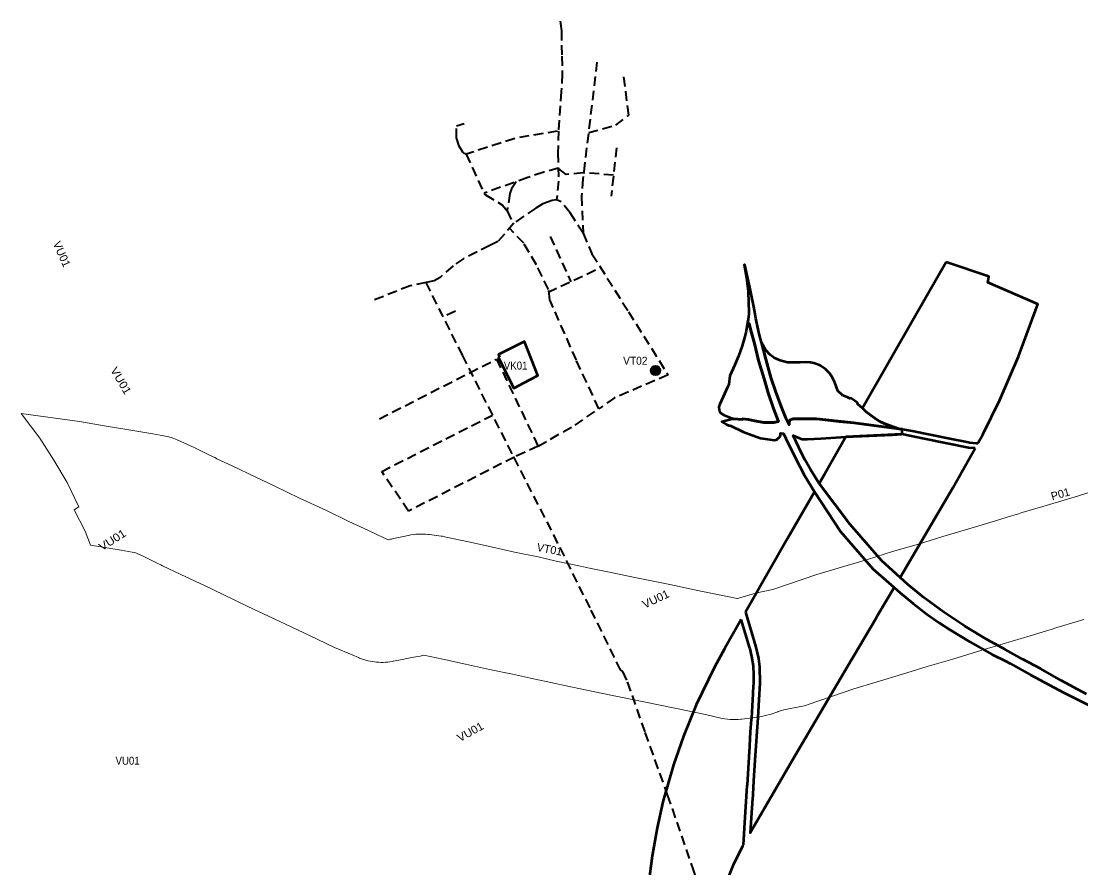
# Model space of a CAD drawing. Extents: x -650145 to -642675, y -1074338 to -1066724.
# Drawn here: x -649600 to -646953, y -1068839 to -1066724 of the extents above; entities that cross this region are included whole.
import ezdxf

# ---------------------------------------------------------------- set-up
doc = ezdxf.new("R2010")
doc.units = 0
doc.header["$LTSCALE"] = 8
doc.linetypes.add('MEDIUM_DASHED', pattern=[4.5, 3, -1.5])
for name, color, linetype in [('1', 7, 'Continuous'), ('17', 7, 'Continuous'), ('2', 7, 'Continuous')]:
    doc.layers.add(name, color=color, linetype=linetype)
for name, color, linetype, lineweight in [('12', 7, 'MEDIUM_DASHED', 40), ('15', 7, 'Continuous', 13), ('44', 7, 'Continuous', 53), ('45', 7, 'Continuous', 53)]:
    doc.layers.add(name, color=color, linetype=linetype, lineweight=lineweight)

msp = doc.modelspace()

# ---------------------------------------------------------------- hatches: boundary and pattern name
at = {"layer": '15'}
msp.add_hatch(color=256, dxfattribs=at).paths.add_polyline_path([(-648003.776, -1067596.576, 1), (-648027.301, -1067596.576, 1)])

# ---------------------------------------------------------------- linework, layer by layer
at = {"layer": '12'}
for p, q in [((-648112.923, -1067040.185), (-648126.71, -1067161.68)), ((-648278.693, -1067262.163), (-648226.9, -1067375.166)), ((-648165.273, -1067346.538), (-648282.098, -1067400.808)), ((-648515.199, -1067448.468), (-648546.557, -1067463.228))]:
    msp.add_line(p, q, dxfattribs=at)
for points in [[(-648254.111, -1066724.115), (-648250.825, -1066748.213), (-648249.73, -1066811.744), (-648248.971, -1066855.783), (-648251.033, -1066899.78), (-648258.055, -1066998.612), (-648259.37, -1067053.379), (-648258.055, -1067123.482), (-648262.874, -1067170.801), (-648274.266, -1067172.334), (-648297.049, -1067180.221), (-648315.013, -1067191.174), (-648369.562, -1067228.854), (-648409.651, -1067274.641), (-648429.367, -1067284.499), (-648494.475, -1067317.053), (-648521.596, -1067335.324), (-648554.018, -1067364.678), (-648568.696, -1067372.565), (-648588.85, -1067377.165), (-648628.502, -1067385.052), (-648726.865, -1067424.267)], [(-648161.945, -1066826.336), (-648197.181, -1067117.94), (-648200.826, -1067161.68), (-648196.766, -1067253.967), (-648228.816, -1067203.221), (-648251.518, -1067175.177), (-648262.874, -1067170.801)], [(-648182.601, -1067002.513), (-648115.19, -1066984.032), (-648082.101, -1066958.613), (-648096.04, -1066857.23)], [(-648488.5, -1067056.457), (-648493.497, -1067055.091), (-648496.863, -1067051.153), (-648505.895, -1067036.526), (-648512.776, -1067015.949), (-648512.582, -1066985.375), (-648494.033, -1066979.937)], [(-648261.097, -1066998.621), (-648367.277, -1067016.878), (-648488.5, -1067056.457), (-648443.711, -1067154.017)], [(-648258.664, -1067091.005), (-648295.035, -1067101.44), (-648334.906, -1067114.73), (-648443.711, -1067154.017), (-648440.351, -1067157.668), (-648398.143, -1067183.811), (-648386.313, -1067197.539), (-648370.813, -1067230.283)], [(-648120.689, -1067108.619), (-648196.172, -1067102.839), (-648238.811, -1067107.157), (-648258.654, -1067091.57)], [(-648364.124, -1067125.28), (-648375.197, -1067142.997), (-648379.372, -1067154.48), (-648386.313, -1067197.539)], [(-648196.766, -1067253.967), (-648174.431, -1067304.992), (-648083.383, -1067449.946), (-647984.432, -1067607.856), (-648117.975, -1067665.279), (-648157.356, -1067692.42), (-648213.545, -1067571.236), (-648279.612, -1067420.693), (-648282.899, -1067394.398), (-648313.139, -1067332.931), (-648344.694, -1067279.025), (-648380.675, -1067241.546)], [(-648589.741, -1067377.342), (-648498.624, -1067558.559), (-648369.855, -1067814.661), (-648270.948, -1068007.281), (-648177.599, -1068195.293), (-648103.97, -1068344.741), (-648098.419, -1068348.539), (-648086.184, -1068375.018), (-648042.175, -1068501.421), (-647986.295, -1068657.442), (-647921.652, -1068844.799), (-647896.268, -1068918.371), (-647865.117, -1068998.629), (-647819.537, -1069124.409), (-647801.818, -1069175.256), (-647812.644, -1069324.711), (-647825.015, -1069541.552), (-647823.978, -1069584.663), (-647594.109, -1069559.949), (-647342.265, -1069543.531), (-647205.182, -1069541.582), (-647108.806, -1069541.669), (-647047.983, -1069544.191), (-646818.857, -1069568.917)], [(-648705.527, -1067717.518), (-648412.884, -1067568.459), (-648309.025, -1067786), (-648368.053, -1067813.183), (-648633.004, -1067948.289), (-648699.635, -1067849.093), (-648423.205, -1067708.555)], [(-648309.025, -1067786), (-648216.797, -1067733.386), (-648157.356, -1067692.42)]]:
    msp.add_lwpolyline(points, dxfattribs=at)
at = {"layer": '15'}
for points in [[(-649382.683, -1067736.41), (-649454.621, -1067724.642), (-649600.146, -1067704.069)], [(-649600.146, -1067704.069), (-649553.44, -1067766.28), (-649518.25, -1067820.92), (-649485.13, -1067877.09), (-649456.24, -1067937.25), (-649467.89, -1067945.1), (-649440.52, -1067998.08), (-649427.146, -1068033.129), (-649350.073, -1068045.91)], [(-646911.586, -1067895.218), (-646969.855, -1067913.144), (-647032.093, -1067931.929), (-647048.173, -1067936.726), (-647099.576, -1067952.077), (-647114.132, -1067956.487), (-647120.451, -1067958.402), (-647126.241, -1067960.149), (-647166.751, -1067972.422), (-647233.528, -1067992.581), (-647298.314, -1068011.911), (-647358.997, -1068030.632), (-647423.612, -1068049.375), (-647486.376, -1068068.781), (-647550.936, -1068088.002), (-647612.779, -1068106.747), (-647722.769, -1068144.312), (-647762.416, -1068152.578), (-647765.408, -1068153.202), (-647771.336, -1068154.692), (-647774.267, -1068155.557), (-647802.757, -1068163.967), (-647805.815, -1068164.87), (-647810.703, -1068166.542), (-647812.571, -1068166.788), (-647827.9, -1068163.347), (-647906.909, -1068147.095), (-647980.144, -1068131.782), (-648067.22, -1068114.186), (-648126.418, -1068101.998), (-648181.06, -1068090.497), (-648203.256, -1068085.824), (-648264.087, -1068072.869), (-648309.141, -1068062.702), (-648367.602, -1068050.464), (-648426.568, -1068037.47), (-648482.748, -1068025.289), (-648538.58, -1068012.914), (-648541.779, -1068012.205), (-648548.234, -1068011.067), (-648551.482, -1068010.64), (-648580.682, -1068006.8), (-648583.733, -1068006.399), (-648589.862, -1068005.847), (-648596.008, -1068005.548), (-648602.162, -1068005.5), (-648608.312, -1068005.705), (-648614.449, -1068006.163), (-648620.561, -1068006.871), (-648626.64, -1068007.83), (-648629.657, -1068008.433), (-648649.671, -1068012.436), (-648670.491, -1068016.914), (-648675.031, -1068017.89), (-648677.625, -1068018.618), (-648680.26, -1068018.992), (-648683.7, -1068019.718), (-648693.991, -1068015.264), (-648732.758, -1067996.958), (-648781.439, -1067974.125), (-648839.635, -1067946.226), (-648905.118, -1067915.461), (-648966.216, -1067885.853), (-649013.828, -1067863.231), (-649073.136, -1067835.331), (-649111.1, -1067817.381), (-649111.919, -1067816.904), (-649116.61, -1067814.593), (-649129.493, -1067808.246), (-649168.436, -1067789.027), (-649210.538, -1067770.325), (-649214.568, -1067768.535), (-649222.823, -1067765.435), (-649231.246, -1067762.826), (-649239.808, -1067760.715), (-649244.144, -1067759.913), (-649270.928, -1067754.958), (-649346.551, -1067742.368), (-649382.683, -1067736.41)], [(-649350.073, -1068045.91), (-649322.852, -1068050.442), (-649316.134, -1068051.685), (-649295.764, -1068060.733), (-649262.167, -1068077.314), (-649255.583, -1068080.557), (-649251.7, -1068082.747), (-649246.836, -1068085.047), (-649201.104, -1068106.669), (-649142.052, -1068134.449), (-649096.004, -1068156.327), (-649034.322, -1068186.219), (-648968.265, -1068217.254), (-648909.981, -1068245.195), (-648860.502, -1068268.402), (-648817.649, -1068288.636), (-648773.793, -1068307.617), (-648757.876, -1068314.337), (-648755.322, -1068315.416), (-648750.136, -1068317.382), (-648744.882, -1068319.156), (-648739.566, -1068320.735), (-648734.195, -1068322.115), (-648728.777, -1068323.297), (-648723.319, -1068324.277), (-648717.828, -1068325.055), (-648712.312, -1068325.63), (-648706.779, -1068326), (-648701.236, -1068326.166), (-648695.69, -1068326.126), (-648690.15, -1068325.882), (-648684.623, -1068325.433), (-648679.116, -1068324.78), (-648673.637, -1068323.924), (-648670.915, -1068323.395), (-648657.024, -1068320.696), (-648628.18, -1068314.608), (-648619.413, -1068313.366), (-648614.155, -1068312.621), (-648603.771, -1068310.391), (-648594.694, -1068307.758), (-648546.992, -1068318.331), (-648490.632, -1068330.55)], [(-648127.18, -1068408.134), (-648040.556, -1068425.638), (-647967.831, -1068440.845), (-647890.98, -1068456.653), (-647852.243, -1068465.348), (-647849.022, -1068466.071), (-647842.522, -1068467.232), (-647835.978, -1068468.107), (-647829.402, -1068468.692), (-647822.806, -1068468.988), (-647816.203, -1068468.993), (-647809.607, -1068468.707), (-647803.03, -1068468.132), (-647799.757, -1068467.7), (-647755.597, -1068461.87), (-647751.962, -1068461.39), (-647744.747, -1068460.076), (-647737.604, -1068458.41), (-647730.552, -1068456.398), (-647727.079, -1068455.221), (-647712.829, -1068450.391), (-647710.163, -1068449.487), (-647709.521, -1068449.242), (-647695.198, -1068445.014), (-647652.454, -1068436.102), (-647647.917, -1068435.156), (-647638.976, -1068432.708), (-647634.59, -1068431.21), (-647520.761, -1068392.333), (-647464.624, -1068375.318), (-647399.264, -1068355.859), (-647337.508, -1068336.765), (-647272.983, -1068318.048), (-647211.206, -1068298.989), (-647147.292, -1068279.919), (-647079.909, -1068259.578), (-647039.419, -1068247.311), (-647033.609, -1068245.558), (-647027.128, -1068243.593), (-647013.164, -1068239.363), (-646962.367, -1068224.194), (-646945.867, -1068219.271)], [(-648490.632, -1068330.55), (-648430.618, -1068343.776), (-648372.899, -1068355.858), (-648328.353, -1068365.911), (-648265.404, -1068379.316), (-648242.86, -1068384.063), (-648187.562, -1068395.702), (-648127.18, -1068408.134)]]:
    msp.add_lwpolyline(points, dxfattribs=at)
at = {"layer": '15', "lineweight": 35}
msp.add_circle((-648015.538, -1067596.576), 11.762, dxfattribs=at)
at = {"layer": '44'}
for points in [[(-647400.63, -1067756.19), (-647540.208, -1067762.876), (-647593.267, -1067855.425), (-647606.818, -1067879.061)], [(-647217.611, -1067791.149), (-647233.83, -1067789.69), (-647345.11, -1067767.28), (-647400.63, -1067756.19)], [(-647405.026, -1068113.904), (-647273.297, -1067889.981), (-647217.611, -1067791.149)], [(-647606.818, -1067879.061), (-647530.038, -1067980.839), (-647451.024, -1068071.886), (-647405.026, -1068113.904)], [(-647464.94, -1068215.752), (-647461.188, -1068209.373), (-647419.713, -1068138.871), (-647472.338, -1068093.096), (-647553.628, -1067999.427), (-647618.773, -1067899.914), (-647685.819, -1068016.861)], [(-647685.819, -1068016.861), (-647781.346, -1068183.485), (-647791.055, -1068200.507)], [(-647791.055, -1068200.507), (-647765.22, -1068287.94), (-647759.412, -1068313.436)], [(-647801.797, -1068219.34), (-647843.6, -1068292.629), (-647868.214, -1068337.803), (-647914.339, -1068432.512), (-647946.187, -1068510.254), (-647971.074, -1068581.98), (-647997.27, -1068674.747), (-648011.775, -1068739.718), (-648023.914, -1068809.332), (-648030.73, -1068861.213), (-648038.596, -1068968.281)], [(-647771.413, -1068334.626), (-647774.94, -1068311.47), (-647779.55, -1068292.23), (-647780.07, -1068290.53), (-647801.797, -1068219.34)], [(-647768.02, -1068570.36), (-647770.94, -1068622.47), (-647772.85, -1068656.41), (-647773.08, -1068660.57), (-647773.4, -1068665.71), (-647776.5, -1068714.8), (-647778.95, -1068752.433), (-647675.054, -1068572.919), (-647535.844, -1068336.279), (-647464.94, -1068215.752)], [(-647759.412, -1068313.436), (-647758.45, -1068317.66), (-647756.09, -1068337.61), (-647754.99, -1068378.21), (-647757.41, -1068419.98), (-647760.22, -1068463.96), (-647768.02, -1068570.36)], [(-647796.173, -1068782.191), (-647791.77, -1068713.23), (-647786.47, -1068634.37), (-647786.32, -1068632.19), (-647781.85, -1068562.97), (-647781.55, -1068558.38), (-647781.13, -1068551.88), (-647778.24, -1068499.95), (-647775.82, -1068469.74), (-647775.52, -1068464.97), (-647771.74, -1068404.5), (-647771.47, -1068400.07), (-647770.12, -1068377.5), (-647769.92, -1068352.1), (-647770.81, -1068340.29), (-647771.05, -1068337.01), (-647771.413, -1068334.626)], [(-647846.989, -1068896.545), (-647820.883, -1068832.117), (-647797.632, -1068784.713), (-647796.173, -1068782.191)]]:
    msp.add_lwpolyline(points, dxfattribs=at)
at = {"layer": '45'}
for points in [[(-647681.91, -1067732.74), (-647690.09, -1067716.05), (-647702.04, -1067686.86), (-647715.92, -1067648.12), (-647727.37, -1067614.33), (-647740.49, -1067568.67), (-647751.41, -1067526.58), (-647756.55, -1067505.32), (-647759.16, -1067494.01), (-647764.89, -1067466.64), (-647768.5, -1067446.04), (-647778.78, -1067397.1), (-647792.52, -1067332.74), (-647794.54, -1067333.14), (-647788.77, -1067365.03), (-647784.55, -1067398.01), (-647783.21, -1067429.237)], [(-647289.924, -1067326.309), (-647364.024, -1067455.561), (-647499.095, -1067691.163), (-647489.3, -1067700.07)], [(-647210.537, -1067778.594), (-647198.088, -1067756.5), (-647155.592, -1067670.17), (-647108.971, -1067561.55), (-647061.252, -1067430.908), (-647185.93, -1067377.38), (-647183.09, -1067362.16), (-647289.924, -1067326.309)], [(-647783.21, -1067429.237), (-647782.39, -1067448.34), (-647782.5, -1067455.11), (-647784.36, -1067469.6), (-647785.64, -1067477.02), (-647781.85, -1067479.19), (-647777.55, -1067496.95), (-647773.96, -1067508.48), (-647768.5, -1067529.75), (-647758.25, -1067571.79)], [(-647777.55, -1067496.95), (-647781.85, -1067479.19), (-647785.64, -1067477.02), (-647789.39, -1067498.84), (-647792.54, -1067511.85), (-647799.39, -1067535.48)], [(-647768.5, -1067529.75), (-647773.96, -1067508.48), (-647777.55, -1067496.95)], [(-647799.39, -1067535.48), (-647808.71, -1067561.03), (-647817.59, -1067582.4)], [(-647721.05, -1067691.73), (-647734.63, -1067652.57), (-647744.61, -1067617.96), (-647758.25, -1067571.79), (-647768.5, -1067529.75)], [(-647729.802, -1067557.462), (-647740.124, -1067546.265), (-647751.41, -1067526.58), (-647740.49, -1067568.67)], [(-647758.25, -1067571.79), (-647744.61, -1067617.96), (-647734.63, -1067652.57), (-647721.05, -1067691.73), (-647708.71, -1067723.99)], [(-647740.49, -1067568.67), (-647727.37, -1067614.33), (-647715.92, -1067648.12), (-647702.04, -1067686.86), (-647690.09, -1067716.05), (-647681.91, -1067732.74), (-647680.804, -1067720.745), (-647672, -1067718), (-647643, -1067718), (-647617.443, -1067718), (-647614, -1067718)], [(-647620.586, -1067578.478), (-647628.441, -1067576.759), (-647640.087, -1067576.306), (-647654.743, -1067576.996), (-647685.968, -1067576.68), (-647704.458, -1067572.034), (-647719.661, -1067564.884), (-647729.802, -1067557.462)], [(-647817.59, -1067582.4), (-647829.97, -1067610.62), (-647832.8, -1067631.53), (-647835.06, -1067637.01), (-647855.24, -1067681.26), (-647857.51, -1067687.74), (-647856.9, -1067695.97)], [(-647547.663, -1067659.519), (-647560.187, -1067647.458), (-647567.744, -1067627.24), (-647573.605, -1067614.951), (-647580.539, -1067604.432), (-647586.864, -1067597.411), (-647591.227, -1067593.613), (-647604.415, -1067584.047), (-647606.559, -1067583.309), (-647620.586, -1067578.478)], [(-647499.095, -1067691.163), (-647503.97, -1067686.73), (-647510.6, -1067680.86), (-647511.24, -1067677.53), (-647517.74, -1067672.85), (-647520.13, -1067671.13), (-647527.76, -1067665.65), (-647530.82, -1067666.65), (-647536.83, -1067663.64), (-647547.663, -1067659.519)], [(-647856.9, -1067695.97), (-647852.3, -1067703.36), (-647845.74, -1067707.59), (-647821.02, -1067717.33)], [(-647798.17, -1067717.58), (-647783.13, -1067719.68), (-647768.53, -1067722.82), (-647745.41, -1067726.6), (-647732.71, -1067727.02), (-647720.45, -1067726.49), (-647708.71, -1067723.99), (-647721.05, -1067691.73)], [(-647462.45, -1067719.84), (-647474.13, -1067711.81), (-647489.3, -1067700.07), (-647499.095, -1067691.163)], [(-647489.3, -1067700.07), (-647474.13, -1067711.81), (-647462.45, -1067719.84), (-647453.87, -1067724.97), (-647440.81, -1067731.38), (-647408.2, -1067742.37), (-647398.74, -1067743.15)], [(-647821.02, -1067717.33), (-647850.45, -1067724.77), (-647838.18, -1067731.62), (-647832.56, -1067734.22), (-647829.49, -1067734.58)], [(-647829.49, -1067734.58), (-647796.87, -1067750.25), (-647774.54, -1067758.68), (-647753.53, -1067765.58), (-647718.54, -1067770.6), (-647712.01, -1067769.63), (-647712.26, -1067767.28), (-647709.834, -1067766.324), (-647707.985, -1067765.133), (-647706.723, -1067763.999), (-647705.29, -1067762.21), (-647704.447, -1067760.707), (-647703.675, -1067758.576), (-647703.315, -1067756.406), (-647703.4, -1067753.8), (-647695.71, -1067753.9), (-647690.19, -1067766.37), (-647668.13, -1067812.76), (-647643.83, -1067859.13), (-647618.773, -1067899.914), (-647553.628, -1067999.427), (-647472.338, -1068093.096), (-647419.713, -1068138.871), (-647405.71, -1068151.74), (-647372.38, -1068179.01), (-647337.74, -1068205.67), (-647307.39, -1068227.44), (-647281.64, -1068244.34), (-647230.83, -1068274.93), (-647174.56, -1068306.35), (-647142.788, -1068322.462), (-647130.29, -1068328.8), (-647079.16, -1068357.01), (-647032.91, -1068382.51), (-646997.06, -1068401.37), (-646927.06, -1068436.66)], [(-647708.71, -1067723.99), (-647720.45, -1067726.49), (-647732.71, -1067727.02), (-647745.41, -1067726.6), (-647768.53, -1067722.82), (-647783.13, -1067719.68), (-647798.17, -1067717.58), (-647798.5, -1067719.67), (-647821.02, -1067717.33)], [(-647821.02, -1067717.33), (-647798.5, -1067719.67), (-647798.17, -1067717.58)], [(-646938.95, -1068405.8), (-647002.71, -1068371.09), (-647053.75, -1068342.11), (-647099.2, -1068318.27), (-647112.813, -1068310.564), (-647142.41, -1068293.81), (-647186.26, -1068269.45), (-647243.39, -1068235.26), (-647295.47, -1068201.09), (-647347.74, -1068162.54), (-647353.81, -1068157.67), (-647385.13, -1068131.51), (-647405.026, -1068113.904), (-647451.024, -1068071.886), (-647530.038, -1067980.839), (-647606.818, -1067879.061), (-647628.396, -1067844.048), (-647642.29, -1067820.76), (-647650.8, -1067803.28), (-647672.05, -1067758.98), (-647656.469, -1067766.309), (-647649.22, -1067768.38), (-647635.758, -1067768.38), (-647602.885, -1067766.486), (-647540.208, -1067762.876), (-647423.683, -1067757.294), (-647400.63, -1067756.19), (-647398.74, -1067743.15), (-647408.2, -1067742.37), (-647520.145, -1067727.879), (-647614, -1067718), (-647617.443, -1067718), (-647643, -1067718), (-647672, -1067718), (-647680.804, -1067720.745), (-647681.91, -1067732.74)], [(-647614, -1067718), (-647557, -1067724), (-647520.145, -1067727.879), (-647408.2, -1067742.37), (-647440.81, -1067731.38)], [(-647440.81, -1067731.38), (-647453.87, -1067724.97), (-647462.45, -1067719.84)], [(-647398.74, -1067743.15), (-647374.55, -1067747.34), (-647280.78, -1067766.44), (-647237.91, -1067775.18), (-647231.17, -1067776.55), (-647213.92, -1067778.26), (-647210.537, -1067778.594)]]:
    msp.add_lwpolyline(points, dxfattribs=at)
msp.add_lwpolyline([(-648405.41, -1067563.84), (-648408.002, -1067565.219), (-648369.949, -1067640.851), (-648342.697, -1067626.806), (-648328.54, -1067619.51), (-648309.522, -1067609.713), (-648317.43, -1067590), (-648343.41, -1067524.81), (-648408.26, -1067556.58)], close=True, dxfattribs=at)

# ---------------------------------------------------------------- texts
at = {"layer": '1', "width": 0.9}
msp.add_text('VK01', height=20, dxfattribs=at).set_placement((-648394.54, -1067594.58))
at = {"layer": '17', "width": 0.95}
msp.add_text('VT02', height=20, dxfattribs=at).set_placement((-648096.61, -1067582.461))
at = {"layer": '17'}
for s, rotation, p in [('P01', 15.899, (-647024.707, -1067921.547)), ('VT01', 348.908, (-648313.65, -1068047.434))]:
    msp.add_text(s, height=20, rotation=rotation, dxfattribs=at).set_placement(p)
at = {"layer": '2'}
msp.add_text('VU01', height=20, rotation=293.833, dxfattribs=at).set_placement((-649521.27, -1067279.43))
for rotation, width, p in [(300.389, 1.1, (-649378.291, -1067595.604)), (32.546, 1.1, (-649398.133, -1068048.567)), (25.207, 1.05, (-648042.803, -1068191.925)), (29.08, 1.05, (-648504.265, -1068525.557)), (0.068, 0.9, (-649364.51, -1068581.837))]:
    msp.add_text('VU01', height=20, rotation=rotation, dxfattribs=dict(at, width=width)).set_placement(p)

doc.saveas('drawing.dxf')
